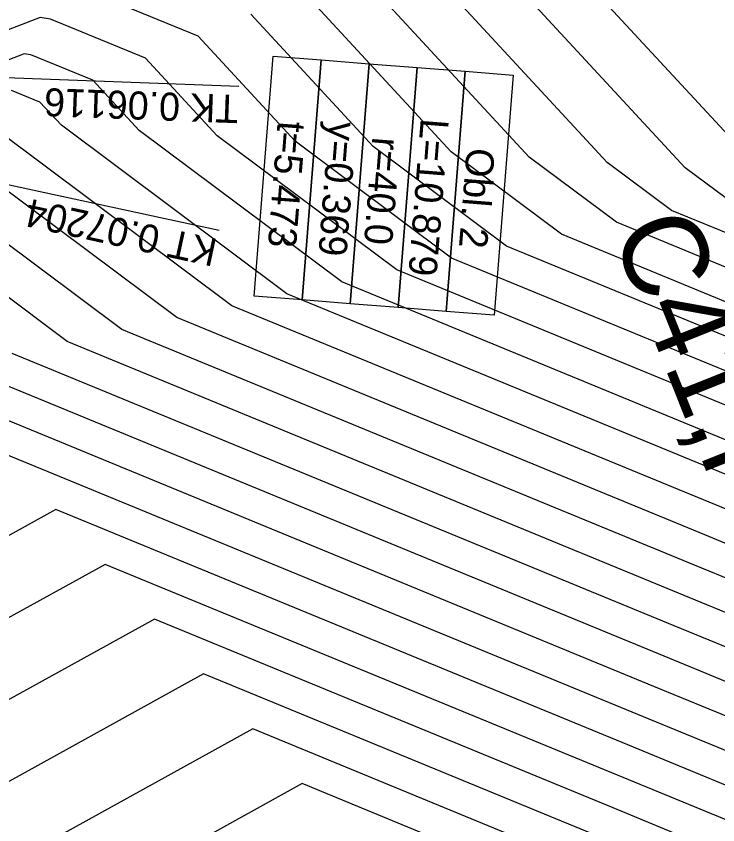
# Model space of a CAD drawing. Extents: x -549394 to -546608, y -1037055 to -1033629.
# Drawn here: x -547425.1 to -547337.6, y -1035992.3 to -1035891.5 of the extents above; entities that cross this region are included whole.
import ezdxf

# ---------------------------------------------------------------- set-up
doc = ezdxf.new("R2010")
doc.units = 0
for name, color, linetype in [('hlavni_vrst', 7, 'Continuous'), ('norm_vrst', 7, 'Continuous'), ('x_popis_oblouky_C41', 7, 'Continuous'), ('x_popis_velky_C41', 7, 'Continuous')]:
    doc.layers.add(name, color=color, linetype=linetype)

msp = doc.modelspace()

# ---------------------------------------------------------------- linework, layer by layer
at = {"layer": 'hlavni_vrst'}
for p, q in [((-547332, -1035911.09), (-547360.95, -1035879.77)), ((-547380.57, -1035907.78), (-547395.81, -1035891.3)), ((-547398.18, -1035927.62), (-547427.9, -1035905.41)), ((-547363.96, -1035920.2), (-547380.57, -1035907.78)), ((-547331.66, -1035933.5), (-547363.96, -1035920.2)), ((-547338, -1035952.4), (-547398.18, -1035927.62)), ((-547344.34, -1035971.31), (-547432.41, -1035935.04)), ((-547309.54, -1035964.1), (-547338, -1035952.4)), ((-547407.84, -1035966.68), (-547427.95, -1035977.79)), ((-547350.68, -1035990.21), (-547407.84, -1035966.68)), ((-547323.91, -1035979.7), (-547344.34, -1035971.31)), ((-547338.28, -1035995.31), (-547350.68, -1035990.21))]:
    msp.add_line(p, q, dxfattribs=at)
at = {"layer": 'norm_vrst'}
for p, q in [((-547341.71, -1035910.43), (-547369.51, -1035880.35)), ((-547351.43, -1035909.77), (-547376.09, -1035883.09)), ((-547361.14, -1035909.11), (-547382.66, -1035885.83)), ((-547402.38, -1035894.04), (-547418.38, -1035887.48)), ((-547370.86, -1035908.45), (-547389.24, -1035888.56)), ((-547422.09, -1035891.73), (-547429.16, -1035894.42)), ((-547420.8, -1035891.93), (-547422.09, -1035891.73)), ((-547408.96, -1035896.78), (-547420.8, -1035891.93)), ((-547390.29, -1035907.12), (-547402.38, -1035894.04)), ((-547424.06, -1035896.24), (-547428.64, -1035897.98)), ((-547423.22, -1035896.37), (-547424.06, -1035896.24)), ((-547415.53, -1035899.52), (-547423.22, -1035896.37)), ((-547400, -1035906.46), (-547408.96, -1035896.78)), ((-547409.72, -1035905.8), (-547415.53, -1035899.52)), ((-547422.1, -1035902.25), (-547425.63, -1035900.81)), ((-547419.43, -1035905.14), (-547422.1, -1035902.25)), ((-547391.34, -1035926.14), (-547419.43, -1035905.14)), ((-547384.49, -1035924.65), (-547409.72, -1035905.8)), ((-547377.65, -1035923.17), (-547400, -1035906.46)), ((-547370.8, -1035921.69), (-547390.29, -1035907.12)), ((-547357.11, -1035918.72), (-547370.86, -1035908.45)), ((-547350.26, -1035917.23), (-547361.14, -1035909.11)), ((-547343.42, -1035915.75), (-547351.43, -1035909.77)), ((-547405.03, -1035929.11), (-547429.31, -1035910.96)), ((-547336.57, -1035914.27), (-547341.71, -1035910.43)), ((-547327.86, -1035922.16), (-547343.42, -1035915.75)), ((-547411.88, -1035930.59), (-547430.73, -1035916.5)), ((-547329.13, -1035925.94), (-547350.26, -1035917.23)), ((-547330.39, -1035929.72), (-547357.11, -1035918.72)), ((-547418.72, -1035932.07), (-547432.14, -1035922.05)), ((-547332.93, -1035937.28), (-547370.8, -1035921.69)), ((-547334.2, -1035941.06), (-547377.65, -1035923.17)), ((-547335.47, -1035944.84), (-547384.49, -1035924.65)), ((-547336.73, -1035948.62), (-547391.34, -1035926.14)), ((-547339.27, -1035956.19), (-547405.03, -1035929.11)), ((-547340.54, -1035959.97), (-547411.88, -1035930.59)), ((-547341.81, -1035963.75), (-547418.72, -1035932.07)), ((-547343.07, -1035967.53), (-547425.57, -1035933.56)), ((-547345.61, -1035975.09), (-547432.38, -1035939.36)), ((-547346.88, -1035978.87), (-547426.24, -1035946.19)), ((-547420.11, -1035953.02), (-547431.34, -1035959.23)), ((-547348.15, -1035982.65), (-547420.11, -1035953.02)), ((-547312.41, -1035967.22), (-547339.27, -1035956.19)), ((-547413.97, -1035959.85), (-547429.64, -1035968.51)), ((-547349.41, -1035986.43), (-547413.97, -1035959.85)), ((-547315.29, -1035970.34), (-547340.54, -1035959.97)), ((-547318.16, -1035973.46), (-547341.81, -1035963.75)), ((-547321.04, -1035976.58), (-547343.07, -1035967.53)), ((-547401.7, -1035973.51), (-547426.25, -1035987.08)), ((-547351.95, -1035993.99), (-547401.7, -1035973.51)), ((-547326.78, -1035982.82), (-547345.61, -1035975.09)), ((-547329.66, -1035985.94), (-547346.88, -1035978.87)), ((-547395.57, -1035980.34), (-547424.56, -1035996.36)), ((-547353.22, -1035997.77), (-547395.57, -1035980.34)), ((-547332.53, -1035989.06), (-547348.15, -1035982.65)), ((-547335.41, -1035992.19), (-547349.41, -1035986.43)), ((-547389.43, -1035987.17), (-547413.67, -1036000.56)), ((-547354.49, -1036001.55), (-547389.43, -1035987.17))]:
    msp.add_line(p, q, dxfattribs=at)
at = {"layer": 'x_popis_oblouky_C41'}
for points in [[(-547387.05, -1035897), (-547389.42, -1035926.9), (-547395.4, -1035926.43), (-547393.03, -1035896.52)], [(-547381.07, -1035897.47), (-547383.44, -1035927.38), (-547389.42, -1035926.9), (-547387.05, -1035897)], [(-547375.09, -1035897.94), (-547377.46, -1035927.85), (-547383.44, -1035927.38), (-547381.07, -1035897.47)], [(-547369.11, -1035898.42), (-547371.48, -1035928.33), (-547377.46, -1035927.85), (-547375.09, -1035897.94)], [(-547363.13, -1035898.89), (-547365.5, -1035928.8), (-547371.48, -1035928.33), (-547369.11, -1035898.42)]]:
    msp.add_lwpolyline(points, close=True, dxfattribs=at)
for points in [[(-547397.33, -1035900.3), (-547438.68, -1035898.78)], [(-547399.75, -1035918.25), (-547440.19, -1035909.52)]]:
    msp.add_lwpolyline(points, dxfattribs=at)

# ---------------------------------------------------------------- texts
for s, rotation, p in [('TK 0.06116', 177.8934, (-547397.31, -1035901.39)), ('t=5.473', 265.4896, (-547392.46, -1035904.55)), ('y=0.369', 265.4896, (-547386.09, -1035904.58)), ('L=10.879', 265.4896, (-547374.64, -1035904.21)), ('r=40.0', 265.4896, (-547380.67, -1035906.53)), ('Obl. 2', 265.4896, (-547368.91, -1035907.88)), ('KT 0.07204', 167.8189, (-547399.81, -1035919.35))]:
    msp.add_text(s, height=3.5, rotation=rotation, dxfattribs=at).set_placement(p)
at = {"layer": 'x_popis_velky_C41'}
msp.add_text('C41,P3,5/30', height=10.5, rotation=291.7026, dxfattribs=at).set_placement((-547350.98, -1035918.38))

doc.saveas('drawing.dxf')
